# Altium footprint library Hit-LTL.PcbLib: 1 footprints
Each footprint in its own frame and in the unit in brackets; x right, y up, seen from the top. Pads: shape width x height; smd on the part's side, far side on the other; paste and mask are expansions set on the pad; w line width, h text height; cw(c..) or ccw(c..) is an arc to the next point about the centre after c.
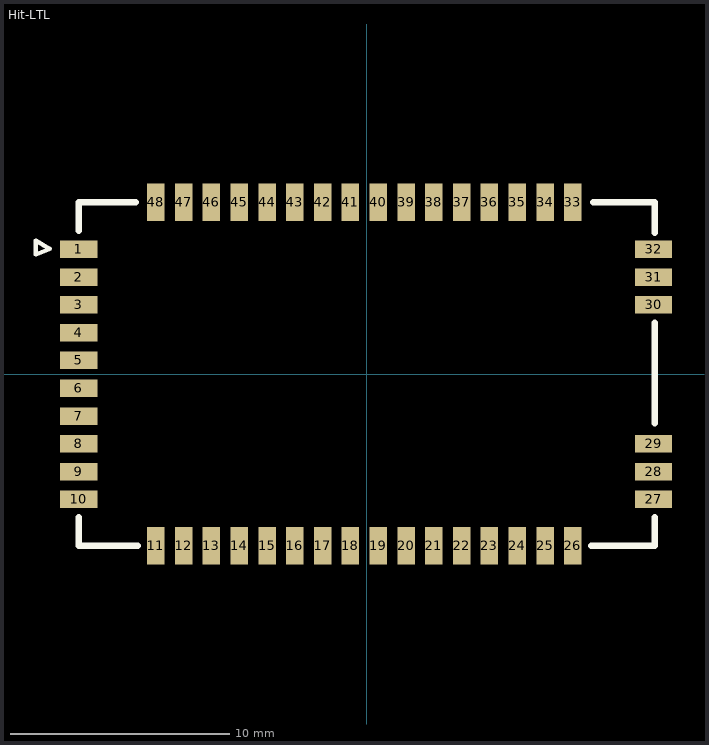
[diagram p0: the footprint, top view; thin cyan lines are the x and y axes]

## Hit-LTL [mm]
pads (48):
  rect 1.7x0.8 smd: 1(-13.15,5.7) 2(-13.15,4.43) 3(-13.15,3.16) 4(-13.15,1.89) 5(-13.15,0.62) 6(-13.15,-0.65) 7(-13.15,-1.92) 8(-13.15,-3.19) 9(-13.15,-4.46) 10(-13.15,-5.73) 27(13.105,-5.73) 28(13.105,-4.46) 29(13.105,-3.19) 30(13.105,3.16) 31(13.105,4.43) 32(13.105,5.7)
  rect 0.8x1.7 smd: 11(-9.63,-7.85) 12(-8.36,-7.85) 13(-7.09,-7.85) 14(-5.82,-7.85) 15(-4.55,-7.85) 16(-3.28,-7.85) 17(-2.01,-7.85) 18(-0.74,-7.85) 19(0.53,-7.85) 20(1.8,-7.85) 21(3.07,-7.85) 22(4.34,-7.85) 23(5.61,-7.85) 24(6.88,-7.85) 25(8.15,-7.85) 26(9.42,-7.85) 33(9.42,7.85) 34(8.15,7.85) 35(6.88,7.85) 36(5.61,7.85) 37(4.34,7.85) 38(3.07,7.85) 39(1.8,7.85) 40(0.53,7.85) 41(-0.74,7.85) 42(-2.01,7.85) 43(-3.28,7.85) 44(-4.55,7.85) 45(-5.82,7.85) 46(-7.09,7.85) 47(-8.36,7.85) 48(-9.63,7.85)
Top Overlay:
  lines w0.2: -15.113,5.461 -15.113,6.096 -14.478,5.715 -15.113,5.461
  lines w0.3: -13.15,-6.55 -13.15,-7.85 -10.45,-7.85 ; -13.15,6.55 -13.15,7.85 -10.55,7.85 ; 10.25,-7.85 13.15,-7.85 13.15,-6.55 ; 10.35,7.85 13.15,7.85 13.15,6.45 ; 13.15,-2.25 13.15,2.35
Mechanical 6:
  text "10" at -13.15,-6.238 h0.64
